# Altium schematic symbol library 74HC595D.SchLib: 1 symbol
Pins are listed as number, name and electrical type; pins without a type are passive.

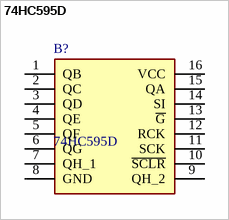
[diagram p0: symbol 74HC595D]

## 74HC595D
designator B?
Shift Register Single 8-Bit Serial to Serial/Parallel 16-Pin SOIC T/R; Manufacturer_Name: Toshiba; Geometry.Height: 1.75mm
footprint SOIC127P600X175-16N
pins: 1 QB, 2 QC, 3 QD, 4 QE, 5 QF, 6 QG, 7 QH_1, 8 GND, 9 QH_2, 10 ~{SCLR}, 11 SCK, 12 RCK, 13 ~{G}, 14 SI, 15 QA, 16 VCC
